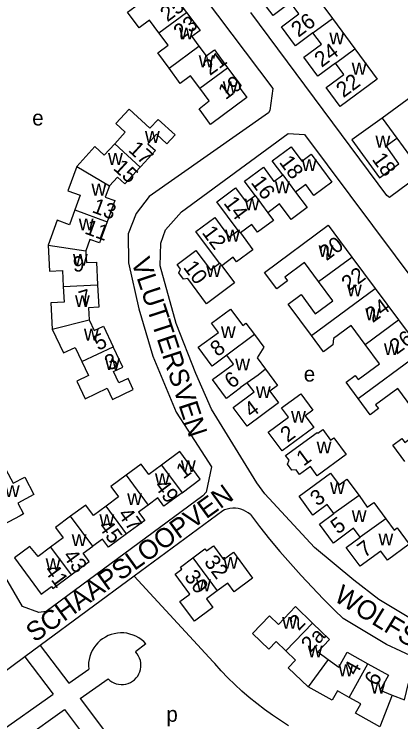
# Model space of a CAD drawing. Extents: x 162667 to 164645, y 379003 to 382150.
# Drawn here: x 163696.1 to 163796.8, y 381105.4 to 381289.7 of the extents above; entities that cross this region are included whole.
import ezdxf

# ---------------------------------------------------------------- set-up
doc = ezdxf.new("R2010")
doc.units = 0
for name, color, linetype in [('BLT_Basislijn', 7, 'Continuous'), ('BLT_Bebouwing', 7, 'Continuous'), ('BLT_Centroide', 7, 'Continuous'), ('BLT_Huisnummer', 7, 'Continuous'), ('BLT_Huisnummer_ tussenligend', 7, 'Continuous'), ('BLT_Onderverdeling_panden', 7, 'Continuous'), ('BLT_Straatnaam', 7, 'Continuous')]:
    doc.layers.add(name, color=color, linetype=linetype)

msp = doc.modelspace()

# ---------------------------------------------------------------- linework, layer by layer
at = {"layer": 'BLT_Basislijn'}
for p, q in [((163721.78, 381325.68), (163763.45, 381270.36)), ((163793.13, 381242.45), (163757.74, 381290.1)), ((163763.45, 381270.36), (163762.71, 381264.6)), ((163762.33, 381263.99), (163731.26, 381242.16)), ((163762.71, 381264.6), (163762.33, 381263.99)), ((163810.21, 381254.21), (163793.87, 381241.9)), ((163731.26, 381242.16), (163727.92, 381237.8)), ((163793.87, 381241.9), (163793.13, 381242.45)), ((163727.92, 381237.8), (163725.85, 381232.44)), ((163725.85, 381232.44), (163725.89, 381224.89)), ((163725.89, 381224.89), (163728.55, 381212.91)), ((163728.55, 381212.91), (163732.22, 381200.58)), ((163732.22, 381200.58), (163738.27, 381186.02)), ((163738.27, 381186.02), (163741.31, 381181.29)), ((163741.31, 381181.29), (163747.51, 381171.74)), ((163747.51, 381171.74), (163746.08, 381165.21)), ((163746.08, 381165.21), (163745.28, 381164.26)), ((163698.35, 381135.41), (163681.89, 381163.26)), ((163745.28, 381164.26), (163704.43, 381134.08)), ((163750.41, 381160.33), (163727.35, 381143.31)), ((163757.62, 381159.34), (163760.02, 381156.23)), ((163727.35, 381143.31), (163702.93, 381125.28)), ((163747.93, 381121.02), (163727.35, 381143.31)), ((163702.59, 381133.83), (163698.35, 381135.41)), ((163704.43, 381134.08), (163702.59, 381133.83)), ((163702.93, 381125.28), (163698.9, 381122.3)), ((163702.93, 381125.28), (163710.35, 381115.41)), ((163730.44, 381125.65), (163727.68, 381123.61)), ((163698.9, 381122.3), (163688.93, 381114.94)), ((163698.9, 381122.3), (163706.26, 381112.53)), ((163710.35, 381115.41), (163715.53, 381119.07)), ((163713.36, 381111.42), (163720.6, 381116.53)), ((163686.19, 381098.35), (163706.26, 381112.53)), ((163713.36, 381111.42), (163737.35, 381079.53)), ((163688.46, 381093.84), (163709.27, 381108.53)), ((163709.27, 381108.53), (163733.36, 381076.52))]:
    msp.add_line(p, q, dxfattribs=at)
for points in [[(163822.31, 381130.67), (163818.31, 381128.09), (163813.89, 381126.98), (163812.29, 381126.9), (163806.46, 381127.93), (163791.01, 381137.26), (163784.57, 381142.27), (163774.34, 381150.78), (163761.37, 381164.77), (163759.3, 381167.59), (163747.46, 381186.8), (163743.42, 381196.09), (163738.32, 381209.11), (163734.13, 381224.16), (163734.29, 381230.05), (163735.56, 381233.49), (163739.65, 381238.21), (163767.49, 381258.57), (163771.7, 381258.34), (163830.43, 381179.71)], [(163757.62, 381159.34), (163757.06, 381159.8), (163756.46, 381160.18), (163755.81, 381160.5), (163755.14, 381160.74), (163754.44, 381160.91), (163753.73, 381161), (163753.01, 381161.01), (163752.3, 381160.94), (163751.6, 381160.79), (163750.92, 381160.56), (163750.41, 381160.33)], [(163760.02, 381156.23), (163762.62, 381152.97), (163765.29, 381149.75), (163768.02, 381146.59), (163770.81, 381143.48), (163773.66, 381140.42), (163776.56, 381137.42), (163779.52, 381134.47), (163781.81, 381132.27)], [(163800.54, 381122.04), (163793.08, 381125.51), (163781.81, 381132.27)], [(163730.44, 381125.65), (163729.86, 381126.24), (163729.23, 381126.77), (163728.55, 381127.24), (163727.83, 381127.64), (163727.07, 381127.97), (163726.28, 381128.23), (163725.47, 381128.41), (163724.65, 381128.51), (163723.83, 381128.53), (163723, 381128.46), (163722.19, 381128.32), (163721.39, 381128.11), (163720.62, 381127.81), (163719.87, 381127.45), (163719.17, 381127.01), (163718.51, 381126.51), (163717.91, 381125.94), (163717.36, 381125.32), (163716.88, 381124.65), (163716.46, 381123.94), (163716.11, 381123.19), (163715.84, 381122.41), (163715.64, 381121.61), (163715.52, 381120.79), (163715.48, 381119.96), (163715.53, 381119.07)], [(163729.14, 381120.08), (163729.1, 381120.71), (163728.98, 381121.33), (163728.79, 381121.93), (163728.52, 381122.5), (163728.18, 381123.04), (163727.77, 381123.52), (163727.68, 381123.61)], [(163767.58, 381104.34), (163765.44, 381105.68), (163763.34, 381107.08), (163761.28, 381108.55), (163759.27, 381110.09), (163757.31, 381111.68), (163755.41, 381113.34), (163753.55, 381115.06), (163751.76, 381116.84), (163750.02, 381118.67), (163748.33, 381120.55), (163747.93, 381121.02)], [(163720.6, 381116.53), (163721.04, 381116.14), (163721.56, 381115.79), (163722.12, 381115.49), (163722.72, 381115.28), (163723.33, 381115.14), (163723.96, 381115.08), (163724.6, 381115.09), (163725.22, 381115.19), (163725.83, 381115.37), (163726.41, 381115.62), (163726.95, 381115.94), (163727.45, 381116.33), (163727.9, 381116.78), (163728.29, 381117.28), (163728.61, 381117.82), (163728.85, 381118.4), (163729.03, 381119.01), (163729.12, 381119.64), (163729.14, 381120.08)]]:
    msp.add_lwpolyline(points, dxfattribs=at)
at = {"layer": 'BLT_Bebouwing'}
for p, q in [((163773.17, 381296.45), (163778.99, 381288.56)), ((163778.99, 381288.56), (163784.83, 381280.66)), ((163799.76, 381268.31), (163791.94, 381262.64)), ((163714.8, 381228.07), (163714.83, 381227.29)), ((163784.02, 381226.43), (163790.1, 381218.23)), ((163790.1, 381218.23), (163796.17, 381210.03)), ((163796.17, 381210.03), (163802.23, 381201.84))]:
    msp.add_line(p, q, dxfattribs=at)
for points in [[(163768.09, 381292.69), (163763.51, 381289.31), (163759.84, 381294.28), (163769.51, 381301.41), (163773.17, 381296.45)], [(163733.81, 381284.85), (163731.4, 381288.12), (163728.69, 381286.13), (163725.67, 381290.23), (163729.43, 381293), (163733.46, 381295.97), (163735.43, 381293.29), (163737.56, 381294.85), (163741.02, 381290.16)], [(163773.91, 381284.8), (163769.33, 381281.42), (163765.68, 381286.36), (163770.27, 381289.74), (163768.09, 381292.69)], [(163741.02, 381290.16), (163744.54, 381285.41), (163742.41, 381283.84), (163744.24, 381281.36)], [(163736.44, 381275.62), (163733.52, 381279.58), (163736.22, 381281.57), (163733.81, 381284.85)], [(163779.74, 381276.91), (163775.16, 381273.52), (163771.5, 381278.48), (163776.09, 381281.86), (163773.91, 381284.8)], [(163744.24, 381281.36), (163746.12, 381278.81), (163748.25, 381280.38), (163751.7, 381275.71)], [(163784.83, 381280.66), (163790.66, 381272.76), (163780.99, 381265.62), (163777.33, 381270.58), (163781.92, 381273.96), (163779.74, 381276.91)], [(163744.47, 381270.38), (163742.06, 381273.65), (163739.36, 381271.66), (163736.44, 381275.62)], [(163751.7, 381275.71), (163755.19, 381270.98), (163754.7, 381270.64), (163756.67, 381267.98), (163747.22, 381260.97), (163744.25, 381264.99), (163746.88, 381267.11), (163744.47, 381270.38)], [(163722.32, 381255.93), (163725.06, 381258.92), (163722.6, 381261.18), (163726.04, 381264.94), (163731.48, 381259.96), (163733.62, 381262.29), (163738.02, 381258.24), (163735.9, 381255.92), (163733.16, 381258.39), (163730.94, 381255.93), (163732.89, 381254.17), (163729.08, 381250), (163728.94, 381249.86)], [(163791.94, 381262.64), (163784.06, 381256.94), (163791.21, 381247.06), (163796.29, 381250.74), (163792.92, 381255.4), (163795.72, 381257.43)], [(163795.72, 381257.43), (163799.03, 381252.85), (163804.06, 381256.49), (163800.68, 381261.16), (163803.47, 381263.18)], [(163722.32, 381255.93), (163719.58, 381252.93), (163717.11, 381255.21), (163712.43, 381250)], [(163766.05, 381247.83), (163763.32, 381251.51), (163768.23, 381255.16), (163771.01, 381251.41), (163773.41, 381253.2), (163778.81, 381245.94), (163774.15, 381242.48), (163772.05, 381245.31), (163769.4, 381243.33)], [(163712.43, 381250), (163710.14, 381243.71), (163713.32, 381242.55), (163711.92, 381238.69)], [(163728.94, 381249.86), (163724.96, 381245.49), (163723.01, 381247.27), (163720.91, 381244.97)], [(163758.84, 381242.47), (163756.09, 381246.16), (163761, 381249.81), (163763.74, 381246.11), (163766.05, 381247.83)], [(163720.91, 381244.97), (163719.85, 381242.03), (163722.35, 381241.13), (163720.34, 381235.62)], [(163754.41, 381233.37), (163748.88, 381240.8), (163753.76, 381244.43), (163756.51, 381240.74), (163758.84, 381242.47)], [(163769.4, 381243.33), (163772.37, 381239.33), (163768.2, 381236.23), (163765.2, 381240.26), (163762.14, 381237.98)], [(163711.92, 381238.69), (163710.51, 381234.83), (163707.33, 381235.99), (163704.98, 381229.56)], [(163749.58, 381224.8), (163743.44, 381233.06), (163748.33, 381236.69), (163752.08, 381231.64), (163754.41, 381233.37)], [(163762.14, 381237.98), (163763.63, 381235.98), (163759.49, 381232.9), (163757.98, 381234.93), (163755.02, 381232.73)], [(163720.34, 381235.62), (163718.33, 381230.1), (163715.87, 381231), (163714.8, 381228.07)], [(163775.37, 381220.02), (163771.68, 381224.99), (163766.58, 381221.22), (163767.32, 381220.22), (163764.51, 381218.13), (163761.33, 381222.44), (163777.89, 381234.71), (163784.02, 381226.43)], [(163755.02, 381232.73), (163758.29, 381228.33), (163754.03, 381225.16), (163753.13, 381226.38), (163750.16, 381224.17)], [(163704.98, 381229.56), (163705.32, 381222.72), (163708.73, 381222.88), (163708.93, 381218.76)], [(163714.83, 381227.29), (163714.94, 381224.96), (163717.57, 381225.09), (163717.86, 381219.18)], [(163750.16, 381224.17), (163753.51, 381219.67), (163746.2, 381214.23), (163741.31, 381220.8), (163740.21, 381220.69), (163739.02, 381222.3), (163739.45, 381223.3), (163738.56, 381224.5), (163743.45, 381228.13), (163747.23, 381223.05), (163749.58, 381224.8)], [(163773.52, 381205.96), (163767.45, 381214.16), (163770.82, 381216.66), (163774.51, 381211.67), (163779.05, 381215.04), (163775.37, 381220.02)], [(163708.93, 381218.76), (163709.12, 381214.64), (163705.72, 381214.48), (163706.06, 381207.63)], [(163717.86, 381219.18), (163718.14, 381213.34), (163715.52, 381213.21), (163715.68, 381210.09)], [(163751.47, 381200.85), (163747.68, 381198.02), (163744.05, 381202.91), (163749.3, 381206.81), (163747.53, 381209.2), (163752.46, 381212.85), (163755.62, 381208.6), (163756.47, 381209.23), (163758.67, 381206.26)], [(163715.68, 381210.09), (163717, 381207.29), (163719.36, 381208.4), (163721.9, 381203.04)], [(163706.06, 381207.63), (163709, 381201.43), (163712.03, 381202.86), (163713.75, 381199.2)], [(163787.5, 381203.62), (163783.82, 381208.6), (163779.27, 381205.24), (163779.06, 381203.52), (163776.65, 381201.74), (163773.52, 381205.96)], [(163758.67, 381206.26), (163761.11, 381202.98), (163759.36, 381200.18), (163761.57, 381197.21)], [(163785.66, 381189.56), (163782.53, 381193.79), (163784.91, 381195.55), (163785.66, 381194.55), (163791.19, 381198.64), (163787.5, 381203.62)], [(163713.75, 381199.2), (163715.48, 381195.54), (163712.45, 381194.11), (163714.62, 381189.51), (163720.36, 381192.23), (163721.69, 381189.35), (163727.14, 381191.92), (163725.81, 381194.79), (163723.42, 381193.64), (163722, 381196.65), (163724.4, 381197.75), (163721.9, 381203.04)], [(163756.81, 381193.67), (163755.04, 381192.41), (163755.09, 381192.33), (163751.41, 381189.6), (163747.79, 381194.49), (163753.2, 381198.52), (163751.47, 381200.85)], [(163761.57, 381197.21), (163764.72, 381192.96), (163762.72, 381191.47), (163764.98, 381188.42), (163756.8, 381182.35), (163753.15, 381187.27), (163758.57, 381191.32), (163756.81, 381193.67)], [(163799.64, 381187.22), (163795.96, 381192.19), (163790.21, 381187.94), (163790.96, 381186.93), (163788.8, 381185.33), (163785.66, 381189.56)], [(163770.72, 381190.8), (163773.88, 381186.53), (163771.86, 381185.04), (163774.12, 381181.98), (163765.9, 381175.91), (163762.28, 381180.82), (163767.53, 381184.7), (163765.74, 381187.12), (163770.72, 381190.8)], [(163797.8, 381173.16), (163794.67, 381177.39), (163797.05, 381179.16), (163797.8, 381178.15), (163803.33, 381182.24), (163799.64, 381187.22)], [(163774.98, 381180.76), (163775.15, 381180.53), (163776.45, 381181.5), (163778.49, 381178.71)], [(163778.48, 381178.71), (163779.33, 381179.33), (163782.51, 381175.03), (163775, 381169.47), (163773.23, 381171.88), (163770.42, 381169.8), (163769.53, 381170.99), (163768.43, 381170.88), (163767.24, 381172.5), (163767.68, 381173.51), (163766.79, 381174.69), (163774.98, 381180.76)], [(163739.83, 381165.04), (163744.55, 381168.53), (163739.23, 381175.74), (163734.5, 381172.24)], [(163734.5, 381172.24), (163731.23, 381169.81), (163729.22, 381172.51), (163725.27, 381169.59)], [(163694.01, 381171.08), (163695.92, 381167.49), (163698.9, 381169.07), (163701.3, 381164.56), (163697.08, 381162.31), (163698.58, 381159.5), (163697.69, 381159.03), (163693.28, 381156.68), (163691.77, 381159.46), (163692.73, 381159.96), (163691.21, 381162.88), (163688.91, 381161.69), (163686.12, 381166.89)], [(163779.34, 381159.59), (163777.62, 381161.93), (163773.9, 381159.19), (163770.29, 381164.1), (163778.49, 381170.15), (163780.75, 381167.09), (163782.76, 381168.57), (163785.93, 381164.28)], [(163725.27, 381169.59), (163721.32, 381166.66), (163723.33, 381163.96), (163720.06, 381161.54)], [(163739.83, 381165.04), (163735.12, 381161.55), (163733.54, 381163.66), (163731.04, 381161.8)], [(163785.93, 381164.28), (163788.05, 381161.29), (163789.71, 381162.52), (163792.87, 381158.23)], [(163720.06, 381161.54), (163716.8, 381159.12), (163714.79, 381161.82), (163710.84, 381158.89)], [(163731.04, 381161.8), (163728.54, 381159.93), (163730.12, 381157.82), (163725.39, 381154.33)], [(163710.84, 381158.89), (163706.88, 381155.96), (163708.88, 381153.26), (163705.62, 381150.84)], [(163786.2, 381153.42), (163784.49, 381155.76), (163779.27, 381151.93), (163775.64, 381156.86), (163779.34, 381159.59)], [(163792.87, 381158.23), (163795.04, 381155.27), (163795.85, 381155.87), (163798.99, 381151.61), (163793.33, 381147.43), (163791.56, 381149.84), (163786.19, 381145.89), (163782.57, 381150.8), (163786.2, 381153.42)], [(163725.39, 381154.33), (163720.67, 381150.84), (163719.1, 381152.95), (163716.61, 381151.1)], [(163705.62, 381150.84), (163702.36, 381148.42), (163700.26, 381151.05), (163696.24, 381148.08), (163703.19, 381138.62), (163705.85, 381140.61), (163706.2, 381140.11), (163710.95, 381143.64)], [(163710.95, 381143.64), (163715.67, 381147.14), (163714.11, 381149.25), (163716.61, 381151.1)], [(163742.6, 381148.04), (163745.8, 381150.39), (163746.19, 381149.86), (163747.98, 381151.18), (163750.61, 381147.61), (163753.19, 381149.51), (163758.19, 381142.78), (163753.42, 381139.26), (163751.76, 381141.51), (163748.97, 381139.44)], [(163748.97, 381139.44), (163746.17, 381137.37), (163747.82, 381135.14), (163743.06, 381131.61), (163739.29, 381136.69), (163741.89, 381138.62), (163738.02, 381143.83), (163739.8, 381145.15), (163739.4, 381145.68), (163742.6, 381148.04)], [(163766.87, 381123.86), (163764.36, 381126.26), (163762.43, 381124.24), (163758.15, 381128.34), (163762.57, 381132.95), (163764.91, 381130.71), (163769.36, 381135.36), (163773.8, 381131.09)], [(163773.8, 381131.09), (163778.24, 381126.82), (163775.14, 381123.6), (163777.88, 381121.58)], [(163772.64, 381114.46), (163767.43, 381119.44), (163769.37, 381121.46), (163766.87, 381123.86)], [(163777.88, 381121.58), (163780.62, 381119.57), (163782.77, 381123.48), (163788.21, 381120.45)], [(163788.21, 381120.45), (163793.53, 381117.49), (163791.36, 381113.57), (163794.53, 381112.33)], [(163794.53, 381112.33), (163797.7, 381111.09), (163798.76, 381115.43), (163804.74, 381113.93)], [(163783.31, 381111.73), (163780.29, 381113.43), (163778.92, 381110.99), (163772.64, 381114.46)], [(163791.31, 381104.09), (163784.96, 381107.6), (163786.33, 381110.04), (163783.31, 381111.73)]]:
    msp.add_lwpolyline(points, dxfattribs=at)
at = {"layer": 'BLT_Onderverdeling_panden'}
for p, q in [((163733.81, 381284.85), (163741.02, 381290.16)), ((163773.91, 381284.8), (163778.99, 381288.56)), ((163736.44, 381275.62), (163744.24, 381281.36)), ((163779.74, 381276.91), (163784.83, 381280.66)), ((163744.47, 381270.38), (163751.7, 381275.71)), ((163791.94, 381262.64), (163795.72, 381257.43)), ((163722.32, 381255.93), (163728.94, 381249.86)), ((163712.43, 381250), (163720.91, 381244.97)), ((163766.05, 381247.83), (163769.4, 381243.33)), ((163758.84, 381242.47), (163762.14, 381237.98)), ((163711.92, 381238.69), (163720.34, 381235.62)), ((163754.41, 381233.37), (163755.02, 381232.73)), ((163704.98, 381229.56), (163714.8, 381228.07)), ((163775.37, 381220.02), (163784.02, 381226.43)), ((163749.58, 381224.8), (163750.16, 381224.17)), ((163708.93, 381218.76), (163717.86, 381219.18)), ((163773.52, 381205.96), (163790.1, 381218.23)), ((163706.06, 381207.63), (163715.68, 381210.09)), ((163787.5, 381203.62), (163796.17, 381210.03)), ((163758.67, 381206.26), (163751.47, 381200.85)), ((163713.75, 381199.2), (163721.9, 381203.04)), ((163785.66, 381189.56), (163802.23, 381201.84)), ((163734.5, 381172.24), (163739.83, 381165.04)), ((163725.27, 381169.59), (163731.04, 381161.8)), ((163785.93, 381164.28), (163779.34, 381159.59)), ((163725.39, 381154.33), (163720.06, 381161.54)), ((163716.61, 381151.1), (163710.84, 381158.89)), ((163792.87, 381158.23), (163786.2, 381153.42)), ((163705.62, 381150.84), (163710.95, 381143.64)), ((163742.6, 381148.04), (163748.97, 381139.44)), ((163766.87, 381123.86), (163773.8, 381131.09)), ((163777.88, 381121.58), (163772.64, 381114.46)), ((163783.31, 381111.73), (163788.21, 381120.45)), ((163794.53, 381112.33), (163791.31, 381104.09))]:
    msp.add_line(p, q, dxfattribs=at)
msp.add_lwpolyline([(163761.57, 381197.21), (163759.62, 381195.64), (163756.81, 381193.67)], dxfattribs=at)

# ---------------------------------------------------------------- texts
at = {"layer": 'BLT_Centroide'}
for s, p in [('w', (163739.03, 381283.11)), ('w', (163778.17, 381281.84)), ('w', (163744.18, 381275.88)), ('w', (163784, 381273.94)), ('w', (163750.45, 381269.08)), ('e', (163700.84, 381260.69)), ('w', (163730.17, 381256.17)), ('w', (163790.17, 381254.94)), ('w', (163720.56, 381250.44)), ('w', (163770.99, 381248.81)), ('w', (163716.25, 381242.44)), ('w', (163764.02, 381243.03)), ('w', (163756.12, 381238.59)), ('w', (163712.95, 381233.38)), ('w', (163751.06, 381230.44)), ('w', (163775.36, 381226.44)), ('w', (163711.43, 381224.16)), ('w', (163746.12, 381221.19)), ('w', (163782.77, 381216.19)), ('w', (163711.96, 381213.41)), ('w', (163787.52, 381209.97)), ('w', (163714.3, 381204.66)), ('w', (163749.95, 381205.34)), ('w', (163792.38, 381200.88)), ('w', (163719.8, 381197)), ('w', (163753.67, 381196.88)), ('e', (163771.52, 381193.98)), ('w', (163759.06, 381189.69)), ('w', (163768.2, 381183.27)), ('w', (163774.86, 381175.28)), ('w', (163739.53, 381170.39)), ('w', (163732.77, 381167.03)), ('w', (163693.72, 381163.92)), ('w', (163778.35, 381164.66)), ('w', (163725.55, 381161.83)), ('w', (163718.32, 381156.34)), ('w', (163784, 381157.38)), ('w', (163711.11, 381151.14)), ('w', (163790.95, 381151.34)), ('w', (163704.34, 381144.84)), ('w', (163750.53, 381145.22)), ('w', (163743.5, 381139.38)), ('w', (163765.87, 381129.59)), ('w', (163772.55, 381122.16)), ('w', (163780.55, 381117.25)), ('w', (163788.92, 381112.73)), ('p', (163735.75, 381105.37))]:
    msp.add_text(s, height=4, dxfattribs=at).set_placement(p)
at = {"layer": 'BLT_Huisnummer'}
for s, rotation, p in [('25', 36.4024, (163736.02, 381287.55)), ('19', 36.5815, (163751.15, 381267.25)), ('22', 36.4322, (163781.81, 381267.77)), ('17', 317.495, (163725.63, 381254.11)), ('18', 305.8848, (163789.11, 381251.86)), ('18', 306.6361, (163764.95, 381251.11)), ('14', 306.6361, (163750.49, 381240.45)), ('11', 339.8897, (163714.24, 381232.61)), ('12', 306.6361, (163744.86, 381232.76)), ('20', 36.5047, (163777.43, 381225.31)), ('10', 306.6361, (163739.99, 381223.71)), ('7', 16.7524, (163713.69, 381213.52)), ('24', 36.5047, (163789.45, 381209.16)), ('8', 36.4437, (163749.04, 381200.31)), ('3', 24.7524, (163720.83, 381196.76)), ('4', 36.4437, (163757.88, 381184.43)), ('2', 36.4437, (163767.29, 381177.97)), ('1', 36.5134, (163771.46, 381171.8)), ('1', 36.5204, (163740.18, 381168.43)), ('49', 306.6918, (163732.49, 381166.71)), ('3', 36.4067, (163775.05, 381161.36)), ('45', 306.4928, (163717.87, 381156.18)), ('7', 36.3774, (163787.33, 381147.97)), ('32', 306.5939, (163745.4, 381146.95)), ('41', 306.3331, (163703.82, 381144.75)), ('30', 306.5939, (163740.23, 381143.13)), ('2', 46.1875, (163770.19, 381128.91)), ('2a', 46.0696, (163773.27, 381123.28)), ('4', 61.2319, (163785.2, 381117.17))]:
    msp.add_text(s, height=4, rotation=rotation, dxfattribs=at).set_placement(p)
at = {"layer": 'BLT_Huisnummer_ tussenligend'}
for s, rotation, p in [('26', 36.4322, (163770.12, 381283.53)), ('23', 36.5815, (163739.49, 381282.88)), ('24', 36.4322, (163776.16, 381275.69)), ('21', 36.5815, (163747.08, 381273.54)), ('15', 317.495, (163721.7, 381249.37)), ('16', 306.6361, (163757.6, 381245.8)), ('13', 339.8897, (163716.18, 381238.15)), ('9', 1.8897, (163711.48, 381222.59)), ('22', 36.5047, (163783.2, 381217.36)), ('26', 36.5047, (163795.68, 381200.88)), ('5', 24.7524, (163717.98, 381201.97)), ('6', 36.4437, (163752.75, 381191.99)), ('47', 306.4928, (163722.99, 381159.34)), ('5', 36.3882, (163780.38, 381154.09)), ('43', 306.3331, (163708.68, 381148.53)), ('6', 61.0583, (163790.55, 381114.48))]:
    msp.add_text(s, height=4, rotation=rotation, dxfattribs=at).set_placement(p)
at = {"layer": 'BLT_Straatnaam'}
for s, rotation, p in [('VLUTTERSVEN', 288.2142, (163726.57, 381225.34)), ('SCHAAPSLOOPVEN', 35.801, (163701.52, 381125.89)), ('WOLFSVEN', 328.484, (163779.08, 381137.05))]:
    msp.add_text(s, height=5, rotation=rotation, dxfattribs=at).set_placement(p)

doc.saveas('drawing.dxf')
